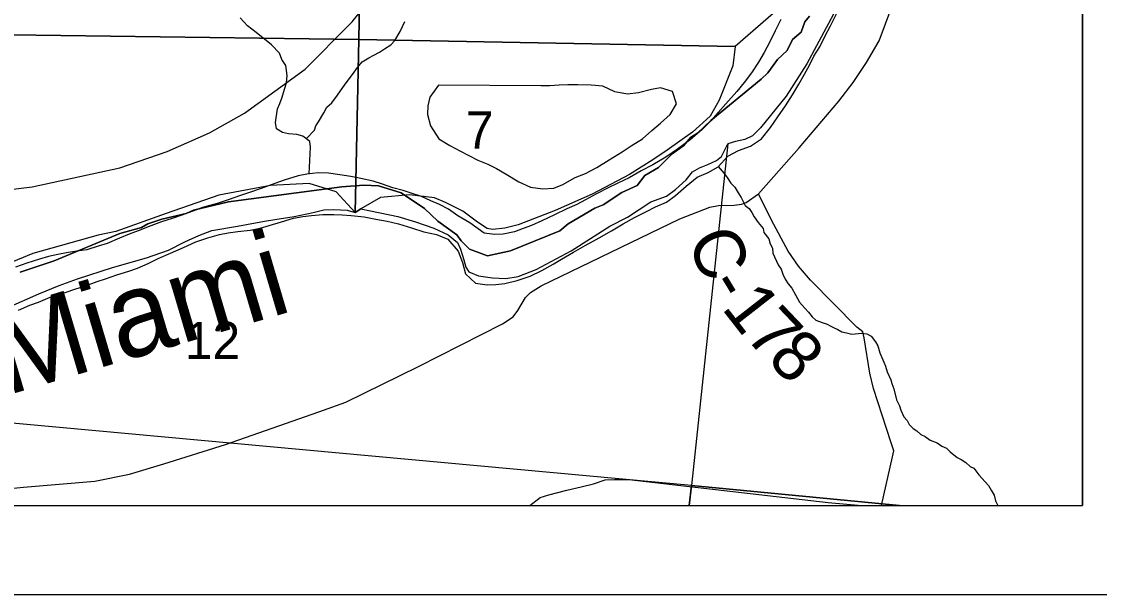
# Model space of a CAD drawing. Extents: x -7.5 to 26.5, y 3.5 to 25.5.
# Drawn here: x 0.251 to 1.462, y 17.5 to 18.144 of the extents above; entities that cross this region are included whole.
import ezdxf

# ---------------------------------------------------------------- set-up
doc = ezdxf.new("R2010")
doc.units = 0
for name, color, linetype in [('GM_X_Corporation', 7, 'Continuous'), ('GM_X_County_Road', 7, 'Continuous'), ('GM_X_County_Road_Text', 7, 'Continuous'), ('GM_X_Major_River', 7, 'Continuous'), ('GM_X_Major_River_Text', 7, 'Continuous'), ('GM_X_Minor_River', 7, 'Continuous'), ('GM_X_Section_Text', 7, 'Continuous'), ('GM_X_State_Route', 7, 'Continuous'), ('SH_Data', 7, 'Continuous')]:
    doc.layers.add(name, color=color, linetype=linetype)

msp = doc.modelspace()

# ---------------------------------------------------------------- linework, layer by layer
at = {"layer": 'GM_X_Corporation'}
for points in [[(-5.2848, 19.2392), (-5.3003, 18.6476), (-5.3247, 17.7117), (-5.3276, 17.6), (1.4431, 17.6), (1.4431, 24.4)], [(1.127, 18.1803), (1.0527, 18.1155), (0.6301, 18.1235), (0.6477, 19.1133)], [(-2.0482, 17.6), (1.4431, 17.6), (1.4431, 18.5934)], [(1.1658, 18.157), (1.1333, 18.0961), (1.1101, 18.0599), (1.0812, 18.0242), (1.0722, 18.0154), (1.0638, 18.011), (1.0531, 18.009), (1.0447, 18.0062), (1.0036, 17.6226), (1.2375, 17.6), (1.4431, 17.6), (1.4431, 18.5971)], [(1.1362, 18.1498), (1.131, 18.1434), (1.1268, 18.1318), (1.1174, 18.1237), (1.1113, 18.111), (1.1003, 18.1012), (1.0895, 18.086), (1.0821, 18.079), (1.0256, 18.0325), (1.0105, 18.0184), (1.0028, 18.0133), (0.9952, 18.0045), (0.982, 17.9951), (0.9667, 17.9796), (0.9512, 17.9707), (0.9428, 17.9596), (0.9255, 17.9518), (0.9045, 17.9377), (0.8953, 17.9342), (0.8654, 17.9163), (0.856, 17.9086), (0.8006, 17.8862), (0.7746, 17.8804), (0.7543, 17.888), (0.7449, 17.8972), (0.7402, 17.9042), (0.7187, 17.9194), (0.704, 17.9336), (0.6776, 17.9512), (0.652, 17.959), (0.6357, 17.9599), (0.611, 17.9581), (0.4836, 17.9412), (0.4442, 17.9319), (0.436, 17.928), (0.4089, 17.9218), (0.3931, 17.9166), (0.3858, 17.9123), (0.3616, 17.9055), (0.2877, 17.875), (0.2497, 17.8623)], [(0.2497, 17.8623), (0.2877, 17.875), (0.3616, 17.9055), (0.3858, 17.9123), (0.3931, 17.9166), (0.4089, 17.9218), (0.436, 17.928), (0.4442, 17.9319), (0.4836, 17.9412), (0.611, 17.9581), (0.6357, 17.9599), (0.652, 17.959), (0.6776, 17.9512), (0.704, 17.9336), (0.7187, 17.9194), (0.7402, 17.9042), (0.7449, 17.8972), (0.7543, 17.888), (0.7746, 17.8804), (0.8006, 17.8862), (0.856, 17.9086), (0.8654, 17.9163), (0.8953, 17.9342), (0.9045, 17.9377), (0.9255, 17.9518), (0.9428, 17.9596), (0.9512, 17.9707), (0.9667, 17.9796), (0.982, 17.9951), (0.9952, 18.0045), (1.0028, 18.0133), (1.0105, 18.0184), (1.0256, 18.0325), (1.0821, 18.079), (1.0895, 18.086), (1.1003, 18.1012), (1.1113, 18.111), (1.1174, 18.1237), (1.1268, 18.1318), (1.131, 18.1434), (1.1362, 18.1498)], [(-0.3746, 18.1372), (0.6301, 18.1235), (0.6258, 17.9292), (0.6047, 17.9524), (0.5743, 17.9619), (0.5307, 17.9596), (0.4728, 17.9488), (0.4136, 17.9279), (0.357, 17.9077), (0.3372, 17.9036), (0.264, 17.8831), (0.2357, 17.8716)], [(0.2352, 17.822), (0.2708, 17.8378), (0.2934, 17.8471), (0.3141, 17.8546), (0.3534, 17.8672), (0.3915, 17.8784), (0.4164, 17.8869), (0.4348, 17.8963), (0.4505, 17.9035), (0.465, 17.9089), (0.4939, 17.9138), (0.524, 17.9196), (0.5358, 17.9212), (0.5575, 17.9248), (0.5788, 17.9292), (0.5906, 17.932), (0.602, 17.9324), (0.6171, 17.9317), (0.6258, 17.9292), (0.6325, 17.9331), (0.6432, 17.9311), (0.6738, 17.9246), (0.6937, 17.9185), (0.7144, 17.9115), (0.7305, 17.9039), (0.7409, 17.8953), (0.7441, 17.8881), (0.748, 17.8759), (0.7504, 17.8678), (0.7537, 17.8625), (0.7646, 17.858), (0.7801, 17.8558), (0.7952, 17.855), (0.8089, 17.8573), (0.8292, 17.8652), (0.8687, 17.8862), (0.9122, 17.9139), (0.9317, 17.9241), (0.9579, 17.9412), (0.9755, 17.9476), (0.9859, 17.9549), (0.9979, 17.966), (1.005, 17.9749), (1.0126, 17.9793), (1.0222, 17.9832), (1.0318, 17.9875), (1.0376, 17.992), (1.0447, 18.0062), (1.0036, 17.6226), (0.0934, 17.7061)]]:
    msp.add_lwpolyline(points, dxfattribs=at)
for points in [[(0.6477, 19.1133), (0.6301, 18.1235), (-0.3746, 18.1372), (-0.3419, 19.1283)], [(0.6301, 18.1235), (1.0527, 18.1155), (1.0503, 18.0939), (1.0349, 18.0553), (1.0247, 18.0374), (1.0049, 18.0193), (0.9764, 17.9991), (0.9602, 17.9882), (0.934, 17.9717), (0.8922, 17.9496), (0.8505, 17.9313), (0.8092, 17.9153), (0.7939, 17.9115), (0.7802, 17.9099), (0.7742, 17.9112), (0.7634, 17.9183), (0.747, 17.9308), (0.7276, 17.9404), (0.7152, 17.9456), (0.6869, 17.9489), (0.6546, 17.9459), (0.6325, 17.9331), (0.6258, 17.9292)], [(-0.0167, 17.6), (1.0012, 17.6), (1.0036, 17.6226), (0.0934, 17.7061), (0.0383, 17.6862), (0.0007, 17.6644), (-0.0109, 17.6548)], [(1.0012, 17.6), (1.2375, 17.6), (1.0036, 17.6226)]]:
    msp.add_lwpolyline(points, close=True, dxfattribs=at)
at = {"layer": 'GM_X_County_Road'}
for points in [[(0.1811, 17.6136), (0.2534, 17.6204), (0.3337, 17.6271), (0.3726, 17.6351), (0.4109, 17.6467), (0.4802, 17.6684), (0.5852, 17.7051), (0.6155, 17.7161), (0.697, 17.7561), (0.7913, 17.8041), (0.8033, 17.8118), (0.8088, 17.8189), (0.8172, 17.8335), (0.823, 17.8394), (0.835, 17.8467), (0.9908, 17.922), (1.0245, 17.9351), (1.0341, 17.9371), (1.0516, 17.9374), (1.0599, 17.9384), (1.0653, 17.9405), (1.0792, 17.95), (1.1247, 18.002), (1.1694, 18.0544), (1.1855, 18.0752), (1.2005, 18.0976), (1.2145, 18.1219), (1.2358, 18.1799)], [(1.2173, 17.6), (1.2295, 17.6548), (1.2312, 17.6612), (1.2277, 17.6715), (1.2081, 17.7313), (1.204, 17.7485), (1.1978, 17.7885), (1.1961, 17.795), (1.1894, 17.8005), (1.1373, 17.8532), (1.1241, 17.8687), (1.1124, 17.8857), (1.0936, 17.9204), (1.0792, 17.95)], [(0.8222, 17.6), (0.8337, 17.6089), (0.8436, 17.6119), (0.8636, 17.617), (0.88, 17.6209), (0.8935, 17.6242), (0.9069, 17.6287), (0.9171, 17.629), (0.9335, 17.629), (1.1572, 17.6035), (1.1952, 17.6)]]:
    msp.add_lwpolyline(points, dxfattribs=at)
at = {"layer": 'GM_X_Major_River'}
for points in [[(0.3814, 17.8666), (0.3933, 17.8719), (0.4045, 17.8773), (0.4184, 17.8833), (0.433, 17.8897), (0.4469, 17.8961), (0.4603, 17.9006), (0.4737, 17.9044), (0.4833, 17.9064), (0.4943, 17.9079), (0.508, 17.9094), (0.5191, 17.9117), (0.5295, 17.9144), (0.5433, 17.9186), (0.5567, 17.9227), (0.567, 17.9247), (0.5769, 17.9259), (0.5895, 17.927), (0.602, 17.927), (0.6115, 17.9267), (0.6213, 17.9257), (0.6361, 17.9244), (0.6493, 17.9218), (0.6618, 17.9195), (0.6746, 17.9164), (0.6893, 17.9118), (0.7032, 17.9075), (0.7175, 17.9044), (0.7299, 17.8991), (0.7416, 17.8858), (0.7465, 17.8728), (0.7499, 17.8601), (0.761, 17.8499), (0.7742, 17.848), (0.7841, 17.8481), (0.794, 17.8493), (0.8078, 17.8527), (0.8224, 17.8575), (0.8355, 17.864), (0.8483, 17.8712), (0.8579, 17.8769), (0.8711, 17.8845), (0.8842, 17.8921), (0.9001, 17.9007), (0.914, 17.9086), (0.9271, 17.9166), (0.9399, 17.9234), (0.9534, 17.9302), (0.9634, 17.9356), (0.9757, 17.9409), (0.9858, 17.9482), (0.9979, 17.9588), (1.01, 17.9687), (1.0223, 17.974), (1.0336, 17.9805), (1.0446, 17.9923), (1.0565, 17.9988), (1.07, 18.0037), (1.0824, 18.0121), (1.0926, 18.0247), (1.1006, 18.0366), (1.1093, 18.0489), (1.1173, 18.0615), (1.1242, 18.0735), (1.1306, 18.0847), (1.1362, 18.0947), (1.1411, 18.1049), (1.1479, 18.1153), (1.1535, 18.1269), (1.16, 18.1388), (1.1665, 18.1523)], [(1.104, 18.1459), (1.0979, 18.1332), (1.0914, 18.1201), (1.0854, 18.1089), (1.079, 18.098), (1.071, 18.0861), (1.0631, 18.0754), (1.0548, 18.065), (1.0422, 18.0513), (1.0336, 18.0417), (1.0253, 18.0321), (1.0155, 18.0221), (1.0022, 18.0108), (0.9882, 18.0005), (0.975, 17.9915), (0.9603, 17.9828), (0.9472, 17.976), (0.9337, 17.968), (0.921, 17.962), (0.9102, 17.957), (0.897, 17.9502), (0.8847, 17.9433), (0.875, 17.9383), (0.8639, 17.9334), (0.85, 17.9266), (0.8357, 17.9198), (0.8242, 17.9144), (0.8146, 17.9113), (0.805, 17.9074), (0.7923, 17.9048), (0.7828, 17.9043), (0.7707, 17.9058), (0.7548, 17.9174), (0.7413, 17.9254), (0.7309, 17.9329), (0.7208, 17.9382), (0.7111, 17.9423), (0.7006, 17.9471), (0.6901, 17.9505), (0.6799, 17.9539), (0.6683, 17.9569), (0.6566, 17.961), (0.6461, 17.9644), (0.6325, 17.9675), (0.6212, 17.9697), (0.6087, 17.9716), (0.5959, 17.9732), (0.5845, 17.9739), (0.5715, 17.9724), (0.562, 17.9704), (0.5462, 17.9656), (0.5359, 17.9617), (0.5205, 17.9561), (0.5063, 17.9512), (0.4959, 17.9478), (0.4844, 17.9439), (0.471, 17.9394), (0.4545, 17.9346), (0.4438, 17.9308), (0.4311, 17.9262)], [(0.4311, 17.9262), (0.4203, 17.9224), (0.4085, 17.9186), (0.3965, 17.914), (0.3823, 17.9087), (0.372, 17.9049), (0.3612, 17.9003), (0.3473, 17.8942), (0.3374, 17.8915), (0.3247, 17.8873), (0.3133, 17.8858), (0.3018, 17.8839), (0.2919, 17.8819), (0.2815, 17.8796), (0.2712, 17.8768), (0.257, 17.8723), (0.2443, 17.8678)], [(0.2478, 17.8195), (0.2605, 17.8251), (0.2701, 17.8283), (0.2832, 17.8339), (0.3012, 17.8398), (0.3112, 17.8429), (0.3231, 17.8468), (0.3361, 17.8517), (0.3457, 17.8548), (0.3584, 17.859), (0.3718, 17.8631), (0.3814, 17.8666)]]:
    msp.add_lwpolyline(points, dxfattribs=at)
at = {"layer": 'GM_X_Minor_River'}
msp.add_line((0.8344, 18.0714), (0.7197, 18.0721), dxfattribs=at)
for points in [[(0.5742, 17.9727), (0.5759, 18.0027), (0.5749, 18.0088), (0.5672, 18.0151), (0.5604, 18.0169), (0.5509, 18.0176), (0.5445, 18.0189), (0.5375, 18.023), (0.5366, 18.0302), (0.5386, 18.0457), (0.5415, 18.0517), (0.544, 18.0589), (0.5466, 18.0679), (0.5487, 18.0747), (0.5494, 18.083), (0.5479, 18.0944), (0.5436, 18.101), (0.5408, 18.108), (0.532, 18.1174), (0.5146, 18.1313), (0.505, 18.1389), (0.4966, 18.1479)], [(0.571, 18.012), (0.5803, 18.0215), (0.5816, 18.0264), (0.5848, 18.0312), (0.5909, 18.0413), (0.5941, 18.0476), (0.5996, 18.0524), (0.606, 18.0609), (0.6148, 18.0735), (0.6231, 18.0842), (0.6287, 18.092), (0.6338, 18.0983), (0.6412, 18.103), (0.647, 18.1058), (0.6532, 18.1094), (0.659, 18.113), (0.666, 18.1177), (0.6707, 18.1225), (0.6764, 18.1326), (0.6817, 18.1438)], [(0.7197, 18.0721), (0.7098, 18.0587), (0.7077, 18.0489), (0.7074, 18.0394), (0.7105, 18.0264), (0.72, 18.0121), (0.7323, 18.0045), (0.7436, 17.9986), (0.7537, 17.9933), (0.7638, 17.9878), (0.7751, 17.9833), (0.7849, 17.9785), (0.7957, 17.9721), (0.8099, 17.9638), (0.8231, 17.9577), (0.8367, 17.9558), (0.8493, 17.9566), (0.8592, 17.9606), (0.8731, 17.9685), (0.8846, 17.9728), (0.8974, 17.9797), (0.9113, 17.9884), (0.926, 17.9975), (0.936, 18.0041), (0.9487, 18.0118), (0.9593, 18.0214), (0.969, 18.0295), (0.9799, 18.0394), (0.987, 18.0514), (0.9825, 18.0652), (0.9689, 18.0694), (0.959, 18.0673), (0.9444, 18.0635), (0.9318, 18.062), (0.9175, 18.0646), (0.9043, 18.0711), (0.8911, 18.0722), (0.8759, 18.0726), (0.8649, 18.0725), (0.855, 18.0724), (0.8447, 18.0715), (0.8344, 18.0714)], [(1.0339, 17.9809), (1.0403, 17.973), (1.044, 17.9683), (1.0479, 17.9621), (1.0523, 17.9577), (1.0563, 17.9512), (1.0595, 17.9461), (1.0641, 17.9372), (1.0686, 17.9336), (1.0715, 17.929), (1.074, 17.9243), (1.0787, 17.9181), (1.0841, 17.9111), (1.0851, 17.9068), (1.0906, 17.8994), (1.0923, 17.8941), (1.0948, 17.889), (1.0953, 17.8833), (1.1013, 17.8702), (1.1046, 17.8655), (1.1063, 17.8598), (1.1091, 17.8543), (1.1124, 17.8489), (1.1164, 17.8442), (1.1207, 17.8365), (1.1249, 17.8283), (1.1312, 17.8217), (1.1352, 17.817), (1.1392, 17.8119), (1.1436, 17.8083), (1.1507, 17.8054), (1.156, 17.8037), (1.1601, 17.8013), (1.1642, 17.7996), (1.1683, 17.7976), (1.1728, 17.7952), (1.178, 17.7938), (1.1837, 17.7925), (1.1951, 17.7936), (1.2008, 17.7927), (1.2056, 17.7902), (1.2104, 17.784), (1.2132, 17.7793), (1.2152, 17.7713), (1.2198, 17.7609), (1.2216, 17.7566), (1.2236, 17.7501), (1.2275, 17.7412), (1.2289, 17.737), (1.2309, 17.7309), (1.2339, 17.7186), (1.2375, 17.712), (1.2388, 17.707), (1.2424, 17.6997), (1.246, 17.6954), (1.2482, 17.6911), (1.2526, 17.6864), (1.2567, 17.684), (1.2614, 17.6797), (1.2663, 17.6776), (1.2719, 17.6732), (1.2797, 17.6703), (1.2849, 17.6667), (1.2901, 17.6642), (1.2942, 17.6603), (1.3023, 17.6539), (1.3068, 17.6515), (1.312, 17.6483), (1.3168, 17.6436), (1.3209, 17.6419), (1.3267, 17.6345), (1.3337, 17.6266), (1.3373, 17.6223), (1.3405, 17.6173), (1.3438, 17.6115), (1.3451, 17.605), (1.3479, 17.6)]]:
    msp.add_lwpolyline(points, dxfattribs=at)
at = {"layer": 'GM_X_State_Route'}
for points in [[(0.6204, 18.1411), (0.6226, 18.1433), (0.6518, 18.1802), (0.6552, 18.1848)], [(0.1954, 17.9497), (0.2633, 17.9581), (0.3615, 17.9795), (0.4149, 17.9977), (0.4623, 18.0185), (0.5015, 18.0409), (0.5698, 18.0902), (0.6204, 18.1411)]]:
    msp.add_lwpolyline(points, dxfattribs=at)
at = {"layer": 'SH_Data'}
for p, q in [((1.4431, 24.4), (1.4431, 17.6)), ((-5.3569, 17.6), (1.4431, 17.6)), ((-5.4569, 17.5), (1.5431, 17.5))]:
    msp.add_line(p, q, dxfattribs=at)

# ---------------------------------------------------------------- texts
at = {"layer": 'GM_X_County_Road_Text'}
for s, rotation, p in [('C', 293.7686, (0.9979, 17.8977)), ('-', 301.2756, (1.0204, 17.8477)), ('1', 307.9637, (1.0367, 17.8218)), ('7', 313.5567, (1.0622, 17.7897)), ('8', 314.9734, (1.0873, 17.7632))]:
    msp.add_text(s, height=0.0568, rotation=rotation, dxfattribs=at).set_placement(p)
at = {"layer": 'GM_X_Major_River_Text'}
msp.add_text('Miami', height=0.09469, rotation=16.4863, dxfattribs=at).set_placement((0.2341, 17.7233))
at = {"layer": 'GM_X_Section_Text'}
for s, height, p in [('7', 0.0419, (0.7503, 18.0008)), ('12', 0.04186, (0.4345, 17.7644))]:
    msp.add_text(s, height=height, rotation=0, dxfattribs=at).set_placement(p)

doc.saveas('drawing.dxf')
